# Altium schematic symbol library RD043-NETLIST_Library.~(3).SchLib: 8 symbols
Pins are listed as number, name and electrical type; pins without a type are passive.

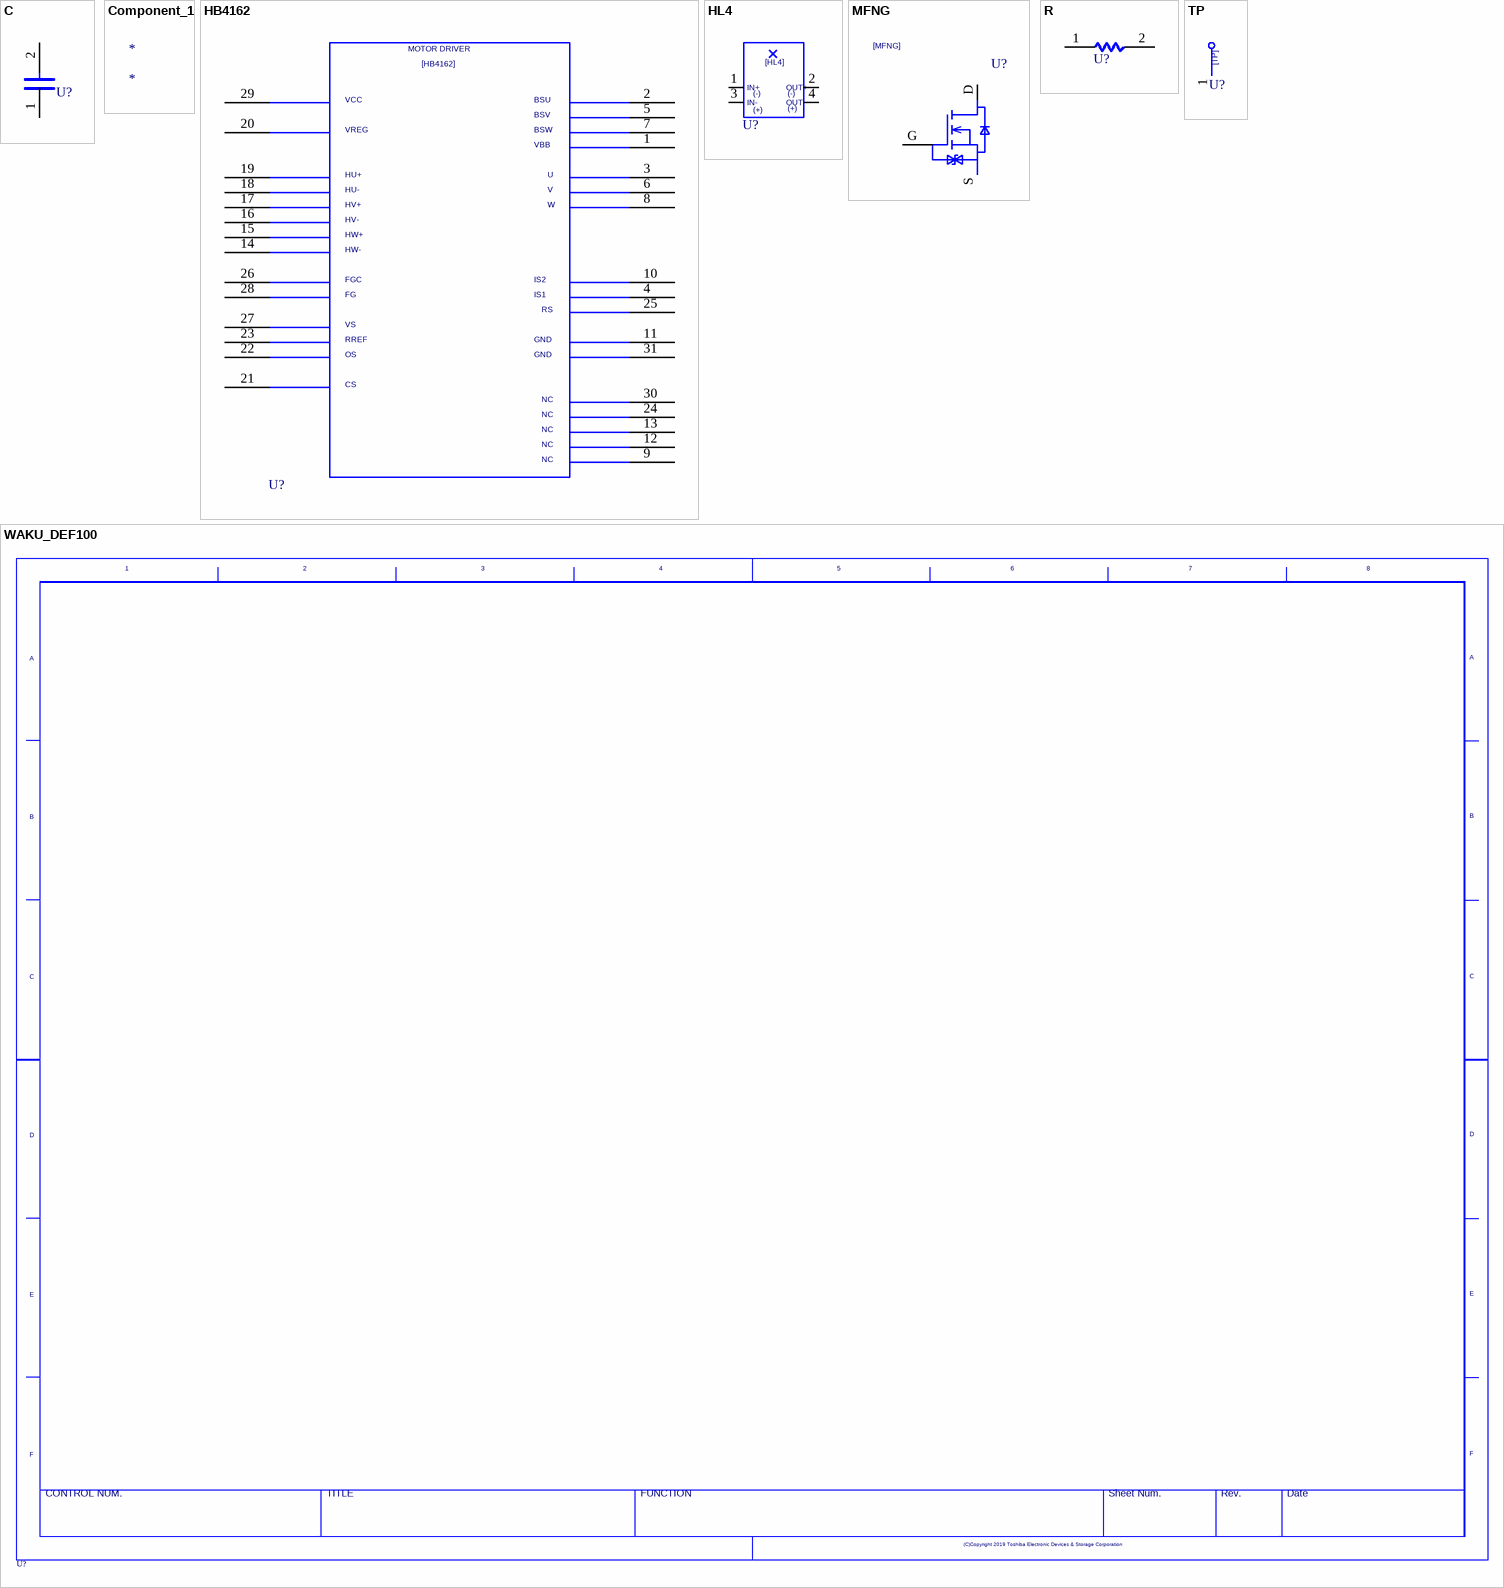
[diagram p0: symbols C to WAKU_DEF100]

## C
designator U?  (value not drawn)
OriginalSymbolOrigin: (2540,7620); Altium-Right: 20; Altium-Bottom: 10
pins: 1, 2

## Component_1
designator *

## HB4162
designator U?  (value not drawn)
SAVEAREA0: -82747,-21522,160014,99323; TIME: 17:23:26; UPDATEUSER: w90028dm; UPDATETIME: 09:08:57; SAVECOUNT: 14; OriginalSymbolOrigin: (7620,76200); Altium-Right: 240; Altium-Bottom: 290
pins: 1, 2, 3, 4, 5, 6, 7, 8, 9, 10, 11, 12, 13, 14, 15, 16, 17, 18, 19, 20, 21, 22, 23, 24, 25, 26, 27, 28, 29, 30, 31

## HL4
designator U?  (value not drawn)
TIME: 12:13:08; UPDATEUSER: e1023210; UPDATETIME: 16:10:58; SAVECOUNT: 25; SAVEAREA0: -742,-353,31311,30816; OriginalSymbolOrigin: (2540,13970); Altium-Right: 40; Altium-Bottom: 50
pins: 1, 2, 3, 4

## MFNG
designator U?  (value not drawn)
SAVECOUNT: 17; SAVEAREA0: -7084,-293,21840,15991; OriginalSymbolOrigin: (5080,12700); Altium-Right: 40; Altium-Bottom: 50
pins: D, G, S

## R
designator U?  (value not drawn)
OriginalSymbolOrigin: (5080,5080); Altium-Right: 20
pins: 1, 2

## TP
designator U?  (value not drawn)
TIME: 16:12:21; UPDATEUSER: fukuda-y; UPDATETIME: 16:18:11; SAVECOUNT: 2; SAVEAREA0: -242,-92,12810,7836; OriginalSymbolOrigin: (0,7620); Altium-Right: 20; Altium-Bottom: 30
pins: 1

## WAKU_DEF100
designator U?  (value not drawn)
PLOTTIME: HH:MM; SAVEAREA0: 198008,-65938,436964,90161; TIME: 14:30:25; UPDATEUSER: d5009410; UPDATETIME: 15:37:05; SAVECOUNT: 4; OriginalSymbolOrigin: (10160,284480); Altium-Right: 1570; Altium-Bottom: 1070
